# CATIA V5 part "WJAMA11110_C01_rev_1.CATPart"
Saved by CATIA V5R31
Part number: WJAMA11110_C01_rev_1
Source: Unknown
Bounding box of the stored display mesh (mm): x 4119.118 to 4134.35, y -529.845 to -478.031, z 633.004 to 657.593
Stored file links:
  \\solize.local\damia\dept\DDE_Design\10_order\2305701_JAMA_変換検証STEP3_お手本モデル作成\work\02_マツダ_板金\10_CATIA_V5\231211\WJAMA11110_C01_rev_1.CATPart
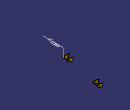
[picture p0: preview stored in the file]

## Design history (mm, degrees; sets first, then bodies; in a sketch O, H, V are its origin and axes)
TTRSSet1
f4a2d38f3ddc11d3a929006094b99c4b_11 "CATTPSSet"
Body1 "MANIFOLD_SOLID_BREP #9753" (main body)
  Solid1: solid without history
Body2 "MANIFOLD_SOLID_BREP #9754"
  Solid2: solid without history
Body3 "MANIFOLD_SOLID_BREP #9755"
  Solid3: solid without history
Body4 "MANIFOLD_SOLID_BREP #9756"
  Solid4: solid without history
